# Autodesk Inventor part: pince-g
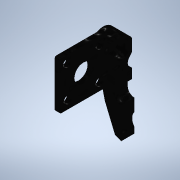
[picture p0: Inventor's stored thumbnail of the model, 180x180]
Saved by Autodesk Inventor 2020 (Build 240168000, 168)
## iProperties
Created: 2023-10
Part Number: pince-g
Material: Générique
Document SubType Name: Modeling
Designer: bruno
Density: 1 g/cm^3
Appearance: Noir
Author: bruno
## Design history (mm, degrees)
sketch "Esquisse1"
  geometry: L1 (-5.917, 4)-(-43.5, 4); L2 (-43.5, 4)-(-43.5, -4); L3 (-43.5, -4)-(-5.917, -4); L4 (-5.917, -4)-(-5.917, 4); C1 r 5 at (0, 0); C2 r 7.5 at (0, 0); 3 further points
  constraints: 8 end point, 2 centre point, 2 coincident, 2 parallel, 1 horizontal, 1 perpendicular
  dimensions: "d0" = 10 diameter of C1; "d1" = 15 diameter of C2; "d2" = 4 distance from line of L3 point (0, 0); "d3" = 4 distance from line of L1 point (0, 0); "d4" = 43.5 distance from line of L2 point (0, 0)
extrude "Extrusion1" new body sketch "Esquisse1" distance "d5" = 15; taper "d6" = 0 deg
sketch "Esquisse2"
  geometry: L1 (15, 37.156)-(15, 0) reference; L2 (0, 0)-(15, 0) reference; L3 (0, 37.156)-(0, 0) reference; L4 (23.715, 19)-(11, 19); L5 (11, 19)-(11, 53.427); L6 (11, 53.427)-(23.715, 53.427); L7 (23.715, 53.427)-(23.715, 19); L8 (15, 0)-(15, 37.156) reference; L9 (15, 0)-(11.265, 1.431); L10 (0, 0)-(0, 37.156) reference; L11 (0, 37.156)-(5.093, 16.193); L12 (5.093, 16.193)-(11.265, 1.431); C1 r 6.035 at (19.697, 7.524); 1 further point
  constraints: 14 end point, 2 parallel, 1 centre point, 1 horizontal, 1 perpendicular
  dimensions: "d7" = 4 distance between parallel lines of L5 L1; "d8" = 19 distance from line of L1.end L4; "d11" = 16 distance of L11.end L9.end; "d12" = 4 distance of L1.end L9.end
extrude "Extrusion2" cut sketch "Esquisse2" stored distance "d9" = 29; taper "d10" = 0 deg
fillet "Congé1" dims "d13" = 4
fillet "Congé2" dims "d14" = 4
sketch "Esquisse3"
  geometry: L1 (6.5, 12.558)-(19.872, 12.558); L2 (19.872, 12.558)-(19.872, -11.726); L3 (19.872, -11.726)-(6.5, -11.726); L4 (6.5, -11.726)-(6.5, 12.558); 1 further point
  constraints: 8 end point, 2 parallel, 1 horizontal, 1 perpendicular
  dimensions: "d45" = 6.5 distance from line of L4 point (0, 0)
extrude "Extrusion3" cut sketch "Esquisse3" distance "d16" = 20; taper "d17" = 0 deg
sketch "Esquisse4"
  geometry: L1 (-5.713, 5.5)-(12.395, 5.5); L2 (0, 0)-(0, 12.239) reference; L3 (0, 8.5)-(0.406, 8.5); L4 (0.406, 2.5)-(0, 2.5); L5 (8, 12.239)-(8, 0) reference; L6 (7.381, 8.5)-(10.512, 8.5); L7 (10.512, 8.5)-(10.512, 2.5); L8 (10.512, 2.5)-(7.381, 2.5); L9 (7.381, 2.5)-(7.381, 8.5); 5 further points
  constraints: 14 end point, 3 horizontal, 3 parallel, 2 point on line, 1 perpendicular
  dimensions: "d18" = 15 distance from line of L1 point (4, 20.5); "d20" = 3 distance from line of L1 L3.start; "d30" = 3 distance between parallel lines of L1 L4
extrude "Extrusion4" join sketch "Esquisse4" stored distance "d22" = 20; taper "d23" = 0 deg
fillet "Congé3" dims "d24" = 4
sketch "Esquisse5"
  geometry: L1 (-8.168, 0)-(-9.626, 6) reference; L2 (0, 0)-(-8.168, 0) reference; L3 (0, 6)-(0, 0) reference; L4 (0, 6)-(-9.626, 6) reference; L5 (0, 3)-(-8.897, 3); L6 (-5.907, -9.307)-(-10.534, 9.739) reference; C1 r 1.5 at (-6.021, 3); 1 further point
  constraints: 2 end point, 2 point on line, 1 centre point, 1 horizontal, 1 midpoint
  dimensions: "d25" = 3 diameter of C1
extrude "Extrusion5" cut sketch "Esquisse5" distance "d26" = 100; taper "d27" = 0 deg
sketch "Esquisse10"
  geometry: C1 r 1.5 at (-14.718, 20.976) reference; 1 further point
extrude "Extrusion10" join sketch "Esquisse10" distance "d46" = 1; taper "d47" = 0 deg
feature "Filetage2" dims "d48" = 9.512, "d49" = 0
sketch "Esquisse11"
  geometry: L1 (-32.5, 35)-(-5.5, 35); L2 (-4.5, 34)-(-4.5, 7); L3 (-5.5, 6)-(-32.5, 6); L4 (-33.5, 7)-(-33.5, 34); L5 (4, 28)-(-4.5, 28); L6 (-1.217, 15.112)-(-4.5, 15.112); C1 r 5.5 at (-19, 20.5); C2 r 2.5 at (-9, 30.12); C3 r 2.5 at (-9.1, 10.6); C4 r 2.5 at (-28.9, 30.4); C5 r 2.5 at (-28.5, 11); A1 r 7.5 centre (4, 20.5) between (10.5, 24.242) and (-1.217, 15.112) reference; A2 r 4 centre (-4, 12.239) between (0, 12.239) and (-1.217, 15.112) reference; A3 r 1 centre (-5.5, 34) between (-4.5, 34) and (-5.5, 35); A4 r 1 centre (-32.5, 34) between (-32.5, 35) and (-33.5, 34); A5 r 1 centre (-32.5, 7) between (-33.5, 7) and (-32.5, 6); A6 r 1 centre (-5.5, 7) between (-5.5, 6) and (-4.5, 7); 1 further point
  constraints: 12 end point, 9 centre point, 9 point on circle, 9 tangent, 3 equal radius, 3 perpendicular, 2 parallel, 2 point on line, 1 horizontal
  dimensions: "d50" = 11 diameter of C1; "d51" = 14.5 distance from line of L4 C1.centre; "d52" = 23 distance of point (4, 20.5) C1.centre; "d53" = 14.5 distance from line of L2 C1.centre; "d54" = 14.5 distance from line of L1 C1.centre; "d55" = 14.5 distance from line of L3 C1.centre; "d56" = 5 diameter of C2; "d57" = 4.5 distance from line of L2 C2.centre; "d58" = 1 radius of A3; "d59" = 5 diameter of C3; "d60" = 4.6 distance from line of L2 C3.centre; "d61" = 4.6 distance from line of C3.centre L3; "d62" = 5 diameter of C4; "d63" = 4.6 distance from line of L4 C4.centre; "d64" = 5 diameter of C5; "d69" = 4.6 distance from line of L1 C4.centre
extrude "Extrusion11" join sketch "Esquisse11" distance "d65" = 3; taper "d66" = 0 deg
fillet "Congé4" dims "d67" = 2
fillet "Congé5" dims "d68" = 2
node "Solide1"
node "Boucle projetée1"
